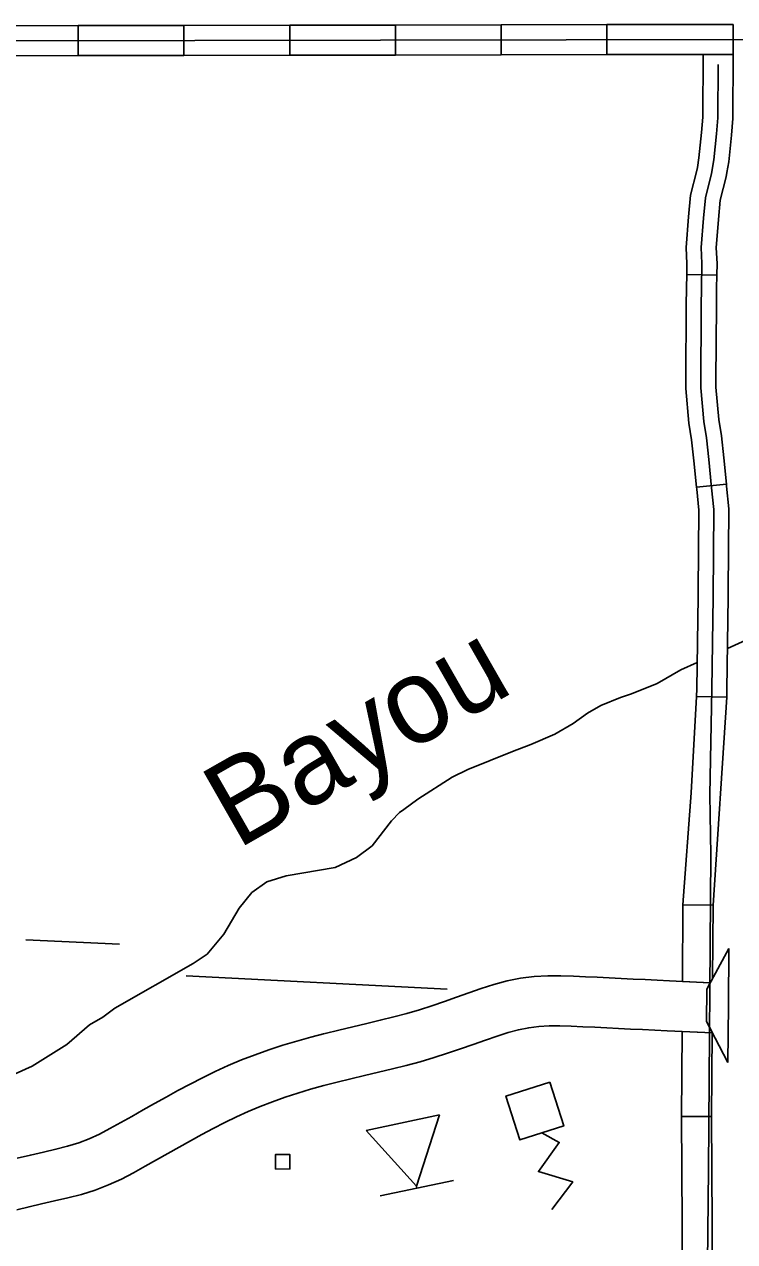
# Model space of a CAD drawing. Extents: x 1366406 to 1373462, y 376856 to 381998.
# Drawn here: x 1369293.3 to 1369350.8, y 380265.6 to 380364.1 of the extents above; entities that cross this region are included whole.
import ezdxf

# ---------------------------------------------------------------- set-up
doc = ezdxf.new("R2010")
doc.units = 0
for name, color, linetype in [('10', 7, 'Continuous'), ('31', 7, 'Continuous'), ('32', 7, 'Continuous'), ('35', 7, 'Continuous'), ('42', 7, 'Continuous'), ('5', 7, 'Continuous'), ('56', 7, 'Continuous'), ('57', 7, 'Continuous')]:
    doc.layers.add(name, color=color, linetype=linetype)

msp = doc.modelspace()

# ---------------------------------------------------------------- linework, layer by layer
at = {"layer": '10'}
for points in [[(1369317.658, 380282.423), (1369318.775, 380282.695), (1369319.9, 380282.968), (1369321.018, 380283.234), (1369322.122, 380283.505), (1369323.212, 380283.777), (1369324.264, 380284.051), (1369325.282, 380284.35), (1369326.296, 380284.677), (1369327.3, 380285.013), (1369328.289, 380285.358), (1369329.273, 380285.707), (1369330.273, 380286.057), (1369331.308, 380286.395), (1369332.381, 380286.68), (1369333.464, 380286.894), (1369334.563, 380287.042), (1369335.66, 380287.108), (1369336.718, 380287.108), (1369337.734, 380287.074), (1369338.713, 380287.024), (1369339.67, 380286.975), (1369340.628, 380286.932), (1369341.599, 380286.886), (1369342.568, 380286.834), (1369343.541, 380286.786), (1369344.525, 380286.735), (1369345.51, 380286.688), (1369348.815, 380286.539), (1369348.538, 380286.024), (1369348.518, 380283.4), (1369348.997, 380282.477)], [(1369292.744, 380272.347), (1369293.822, 380272.599), (1369294.878, 380272.837), (1369295.882, 380273.061), (1369296.824, 380273.308), (1369297.723, 380273.59), (1369298.577, 380273.918), (1369299.41, 380274.296), (1369300.254, 380274.737), (1369301.13, 380275.22), (1369302.024, 380275.727), (1369302.938, 380276.249), (1369303.866, 380276.771), (1369304.798, 380277.291), (1369305.752, 380277.821), (1369306.732, 380278.343), (1369307.73, 380278.856), (1369308.758, 380279.359), (1369309.82, 380279.84), (1369310.903, 380280.288), (1369311.995, 380280.706), (1369313.1, 380281.101), (1369314.225, 380281.473), (1369315.363, 380281.813), (1369316.509, 380282.13), (1369317.639, 380282.418)], [(1369348.997, 380282.477), (1369345.324, 380282.643), (1369344.325, 380282.69), (1369343.336, 380282.741), (1369342.359, 380282.789), (1369341.395, 380282.841), (1369340.441, 380282.886), (1369339.475, 380282.929), (1369338.505, 380282.979), (1369337.562, 380283.028), (1369336.652, 380283.058), (1369335.783, 380283.058), (1369334.954, 380283.008), (1369334.127, 380282.897), (1369333.294, 380282.732), (1369332.457, 380282.51), (1369331.571, 380282.221), (1369330.619, 380281.887), (1369329.632, 380281.537), (1369328.61, 380281.181), (1369327.56, 380280.829), (1369326.473, 380280.479), (1369325.346, 380280.148), (1369324.213, 380279.853), (1369323.095, 380279.573), (1369321.969, 380279.297), (1369320.847, 380279.031), (1369319.733, 380278.76), (1369318.619, 380278.488)], [(1369318.638, 380278.493), (1369317.548, 380278.216), (1369316.483, 380277.921), (1369315.442, 380277.61), (1369314.417, 380277.27), (1369313.4, 380276.907), (1369312.401, 380276.525), (1369311.431, 380276.124), (1369310.484, 380275.695), (1369309.545, 380275.235), (1369308.61, 380274.755), (1369307.688, 380274.263), (1369306.768, 380273.753), (1369305.845, 380273.237), (1369304.934, 380272.725), (1369304.027, 380272.208), (1369303.108, 380271.686), (1369302.17, 380271.169), (1369301.186, 380270.654), (1369300.14, 380270.18), (1369299.055, 380269.764), (1369297.945, 380269.416), (1369296.838, 380269.125), (1369295.764, 380268.885), (1369294.728, 380268.652), (1369293.709, 380268.414), (1369292.714, 380268.158)]]:
    msp.add_lwpolyline(points, dxfattribs=at)
at = {"layer": '31'}
for p, q in [((1369349.334, 380343.785), (1369346.905, 380343.841)), ((1369347.694, 380326.631), (1369350.111, 380326.879)), ((1369347.838, 380318.218), (1369347.838, 380318.218)), ((1369350.139, 380309.637), (1369347.709, 380309.68)), ((1369346.602, 380292.832), (1369349.032, 380292.813)), ((1369348.902, 380275.707), (1369346.472, 380275.725))]:
    msp.add_line(p, q, dxfattribs=at)
for points in [[(1369347.765, 380352.489), (1369347.896, 380353.261), (1369348.102, 380355.332), (1369348.203, 380356.556), (1369348.24, 380361.634), (1369350.671, 380361.639)], [(1369350.671, 380361.639), (1369350.632, 380356.447), (1369350.522, 380355.112), (1369350.306, 380352.936), (1369350.16, 380352.081)], [(1369349.449, 380360.812), (1369349.418, 380356.501), (1369349.312, 380355.222), (1369349.101, 380353.098), (1369348.913, 380351.995), (1369348.422, 380350.041), (1369348.258, 380348.396), (1369348.078, 380346.004), (1369348.14, 380344.715), (1369348.094, 380342.708), (1369348.086, 380341.336), (1369348.046, 380334.664), (1369348.286, 380331.952), (1369348.506, 380330.615), (1369348.685, 380328.872), (1369348.921, 380326.573), (1369349.092, 380324.831), (1369349.051, 380317.765), (1369348.936, 380310.291), (1369348.782, 380301.744), (1369348.862, 380296.875)], [(1369346.905, 380343.841), (1369346.925, 380344.7), (1369346.861, 380346.02), (1369347.047, 380348.502), (1369347.222, 380350.251), (1369347.723, 380352.245), (1369347.765, 380352.489)], [(1369350.16, 380352.081), (1369350.103, 380351.745), (1369349.623, 380349.832), (1369349.468, 380348.29), (1369349.296, 380345.988), (1369349.356, 380344.73), (1369349.334, 380343.785)], [(1369346.905, 380343.841), (1369346.879, 380342.726), (1369346.871, 380341.343), (1369346.835, 380335.267)], [(1369349.334, 380343.785), (1369349.309, 380342.69), (1369349.301, 380341.329), (1369349.265, 380335.253)], [(1369346.835, 380335.267), (1369346.831, 380334.614), (1369347.08, 380331.8), (1369347.301, 380330.454), (1369347.476, 380328.748), (1369347.694, 380326.631)], [(1369349.265, 380335.253), (1369349.262, 380334.714), (1369349.493, 380332.105), (1369349.711, 380330.775), (1369349.894, 380328.996), (1369350.111, 380326.879)], [(1369347.838, 380318.218), (1369347.877, 380324.775), (1369347.712, 380326.452), (1369347.694, 380326.631)], [(1369350.111, 380326.879), (1369350.13, 380326.695), (1369350.307, 380324.887), (1369350.268, 380318.204)], [(1369347.709, 380309.68), (1369347.721, 380310.311), (1369347.836, 380317.778), (1369347.838, 380318.218)], [(1369350.268, 380318.204), (1369350.266, 380317.753), (1369350.15, 380310.271), (1369350.139, 380309.637)], [(1369347.709, 380309.68), (1369347.269, 380301.912), (1369346.602, 380292.832)], [(1369350.139, 380309.637), (1369349.032, 380292.813)], [(1369348.862, 380296.875), (1369348.667, 380271.426), (1369348.553, 380261.33)], [(1369346.555, 380286.641), (1369346.602, 380292.832)], [(1369349.032, 380292.813), (1369348.987, 380286.858), (1369348.815, 380286.539), (1369346.555, 380286.641)], [(1369346.472, 380275.725), (1369346.524, 380282.588)], [(1369346.524, 380282.588), (1369348.953, 380282.479), (1369348.902, 380275.707)], [(1369346.472, 380275.725), (1369346.588, 380258.396)], [(1369348.902, 380275.707), (1369349.018, 380258.375)]]:
    msp.add_lwpolyline(points, dxfattribs=at)
at = {"layer": '32'}
for p, q in [((1369297.687, 380361.535), (1369297.682, 380363.965)), ((1369306.241, 380361.551), (1369306.236, 380363.981)), ((1369314.794, 380361.568), (1369314.79, 380363.998)), ((1369323.348, 380361.585), (1369323.343, 380364.015)), ((1369331.901, 380361.602), (1369331.897, 380364.032)), ((1369340.455, 380361.618), (1369340.45, 380364.048)), ((1369350.671, 380361.639), (1369350.666, 380364.069))]:
    msp.add_line(p, q, dxfattribs=at)
for points in [[(1369289.129, 380363.948), (1369297.682, 380363.965)], [(1369297.682, 380363.965), (1369306.236, 380363.981)], [(1369306.236, 380363.981), (1369314.79, 380363.998)], [(1369314.79, 380363.998), (1369323.343, 380364.015)], [(1369323.343, 380364.015), (1369331.897, 380364.032)], [(1369331.897, 380364.032), (1369340.45, 380364.048)], [(1369340.45, 380364.048), (1369350.666, 380364.069)], [(1369246.581, 380363.074), (1369246.792, 380362.71), (1369247.033, 380362.65), (1369352.161, 380362.856)], [(1369289.134, 380361.518), (1369297.687, 380361.535)], [(1369297.687, 380361.535), (1369306.241, 380361.551)], [(1369306.241, 380361.551), (1369314.794, 380361.568)], [(1369314.794, 380361.568), (1369323.348, 380361.585)], [(1369323.348, 380361.585), (1369331.901, 380361.602)], [(1369331.901, 380361.602), (1369340.455, 380361.618)], [(1369340.455, 380361.618), (1369349.009, 380361.635)]]:
    msp.add_lwpolyline(points, dxfattribs=at)
at = {"layer": '35'}
for points in [[(1369352.641, 380314.683), (1369350.201, 380313.571)], [(1369347.754, 380312.455), (1369346.42, 380311.848), (1369344.502, 380310.752), (1369342.428, 380309.903), (1369341.551, 380309.615), (1369339.963, 380308.955), (1369338.868, 380308.331), (1369337.708, 380307.517), (1369336.226, 380306.646), (1369334.285, 380305.796), (1369332.825, 380305.253), (1369329.192, 380303.788), (1369327.931, 380303.173), (1369325.153, 380301.394), (1369324.011, 380300.558), (1369323.685, 380300.319), (1369323.022, 380299.639), (1369321.46, 380297.611), (1369320.189, 380296.672), (1369318.456, 380295.853), (1369314.501, 380295.186), (1369312.939, 380294.702), (1369311.721, 380293.826), (1369310.691, 380292.569), (1369309.476, 380290.457), (1369308.107, 380288.85), (1369306.976, 380288.095), (1369300.635, 380284.474), (1369299.69, 380283.74), (1369298.595, 380283.121), (1369296.752, 380281.545), (1369293.952, 380279.777), (1369291.738, 380278.796)]]:
    msp.add_lwpolyline(points, dxfattribs=at)
at = {"layer": '42'}
for p, q in [((1369350.313, 380289.318), (1369348.538, 380286.024)), ((1369350.277, 380284.699), (1369350.313, 380289.318)), ((1369348.538, 380286.024), (1369348.518, 380283.4)), ((1369350.242, 380280.08), (1369350.277, 380284.699)), ((1369348.518, 380283.4), (1369350.242, 380280.08))]:
    msp.add_line(p, q, dxfattribs=at)
at = {"layer": '5'}
for points in [[(1369301.029, 380289.644), (1369293.435, 380290.018)], [(1369306.405, 380287.094), (1369327.541, 380286.018)]]:
    msp.add_lwpolyline(points, dxfattribs=at)
at = {"layer": '56'}
msp.add_lwpolyline([(1369313.639, 380271.461), (1369313.631, 380272.632), (1369314.806, 380272.64), (1369314.813, 380271.469)], close=True, dxfattribs=at)
at = {"layer": '57'}
for p, q in [((1369326.92, 380275.849), (1369320.977, 380274.591)), ((1369325.037, 380270.073), (1369326.92, 380275.849)), ((1369320.977, 380274.591), (1369325.037, 380270.073)), ((1369328.043, 380270.543), (1369322.099, 380269.286)), ((1369325.037, 380270.073), (1369325.071, 380269.914))]:
    msp.add_line(p, q, dxfattribs=at)
msp.add_lwpolyline([(1369335.826, 380278.495), (1369336.958, 380274.953), (1369333.416, 380273.822), (1369332.284, 380277.363)], close=True, dxfattribs=at)
msp.add_lwpolyline([(1369335.187, 380274.387), (1369336.595, 380273.624), (1369334.91, 380271.253), (1369337.691, 380270.418), (1369335.997, 380268.188)], dxfattribs=at)

# ---------------------------------------------------------------- texts
at = {"layer": '35'}
msp.add_text('Bayou', height=6.8429, rotation=29.70557, dxfattribs=at).set_placement((1369310.55, 380297.287))

doc.saveas('drawing.dxf')
